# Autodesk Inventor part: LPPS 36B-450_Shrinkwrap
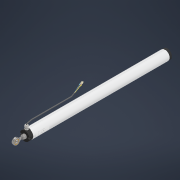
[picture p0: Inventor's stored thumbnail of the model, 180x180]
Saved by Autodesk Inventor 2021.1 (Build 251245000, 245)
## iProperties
Created: 2020-09
Part Number: LPPS 36B-450_Shrinkwrap
Material: Generic
Document SubType Name: Modeling
Designer: J. Nielson
Density: 1 g/cm^3
Appearance: Default
Author: J. Nielson
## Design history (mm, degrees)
derived "LPPS 36B-450.iam"
body "Solid1"
node "LPPS 36B Cable End Cap.iam:1::LPPS-36B PLASTIC CABLE END.ipt"
node "LPPS 36B Cable End Cap.iam:1::LPPS 36B- Cable Gland.ipt:1"
body "Solid2"
node "LPPS 36B Cable End Cap.iam:1::Cable Gland Cap.ipt:1"
body "Solid3"
node "LPPS 36B Cable End Cap.iam:1::Cable.ipt:1"
body "Solid4"
node "LPPS 36B Cable End Cap.iam:1::Cable Gland Seal 1 of 2.ipt:1"
body "Solid5"
node "LPPS 36B Cable End Cap.iam:1::Cable Gland 2 of 2.ipt:1"
body "Solid6"
node "LPPS 36B Cable End Cap.iam:1::#6 Terminal Ring 22 - 18 AWG.i"
body "Solid7"
node "LPPS-36B-450 METAL HOUSING.ipt:1"
body "Solid8"
node "MALE Rod Eye SW.ipt:1"
body "Solid9"
node "LPPS-36B PLASTIC STROKE END.ipt:1"
body "Solid10"
node "LPPS 36B-450 Back Stop.ipt:1"
body "Solid11"
node "LPPS 36B-450 Front Stop.ipt:1"
body "Solid12"
node "AS 1427 - M3 x 16.ipt:1"
body "Solid13"
node "AS 1427 - M3 x 16.ipt:2"
body "Solid14"
node "AS 1427 - M3 x 16.ipt:3"
body "Solid15"
node "AS 1427 - M3 x 16.ipt:4"
body "Solid16"
node "AS 1112 - M8  Type 5.ipt:1"
body "Solid17"
node "AS 1968 - 1976 - 8.ipt:1"
body "Solid18"
node "AS 1237 - 8.ipt:1"
body "Solid19"
